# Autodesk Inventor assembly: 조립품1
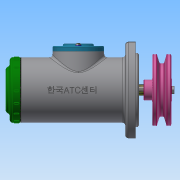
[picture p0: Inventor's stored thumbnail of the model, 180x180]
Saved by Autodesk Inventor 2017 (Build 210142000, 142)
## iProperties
Part Number: 조립품1
Material: 일반
Document SubType Name: Assembly
Designer: user
Author: user
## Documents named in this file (22)
- C:\Users\user\Desktop\720506V1031\조립품1.iam
- C:\Users\user\Desktop\720506V1031\본체.ipt
- C:\Users\user\Desktop\720506V1031\V-벨트풀리.ipt
- C:\Users\user\Desktop\720506V1031\개스킷.ipt
- C:\Users\user\Desktop\720506V1031\너트 M10.ipt
- C:\Users\user\Desktop\720506V1031\멈춤나사 M3.ipt
- C:\Users\user\Desktop\720506V1031\멈춤링 15 x 1.ipt
- C:\Users\user\Desktop\720506V1031\멈춤링 35 x 1.6.ipt
- C:\Users\user\Desktop\720506V1031\베어링 6202.ipt
- C:\Users\user\Desktop\720506V1031\볼트 M4 x 10.ipt
- C:\Users\user\Desktop\720506V1031\부시1.ipt
- C:\Users\user\Desktop\720506V1031\부시2.ipt
- C:\Users\user\Desktop\720506V1031\사이드 커버.ipt
- 사이드 커버.ipt
- C:\Users\user\Desktop\720506V1031\십자볼트 M3 x 10.ipt
- C:\Users\user\Desktop\720506V1031\오일 실 15 x 30 x 7.ipt
- C:\Users\user\Desktop\720506V1031\와셔 3 x 6.ipt
- C:\Users\user\Desktop\720506V1031\와셔 4 x 16.ipt
- C:\Users\user\Desktop\720506V1031\와셔 10 x 21.ipt
- C:\Users\user\Desktop\720506V1031\축.ipt
- C:\Users\user\Desktop\720506V1031\키 4 x 4.ipt
- C:\Users\user\Desktop\720506V1031\탑 커버.ipt
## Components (3 placed, 3 different names)
1. V-벨트풀리:1
2. 개스킷:1
3. ISO 4017 M4 x 10:1
